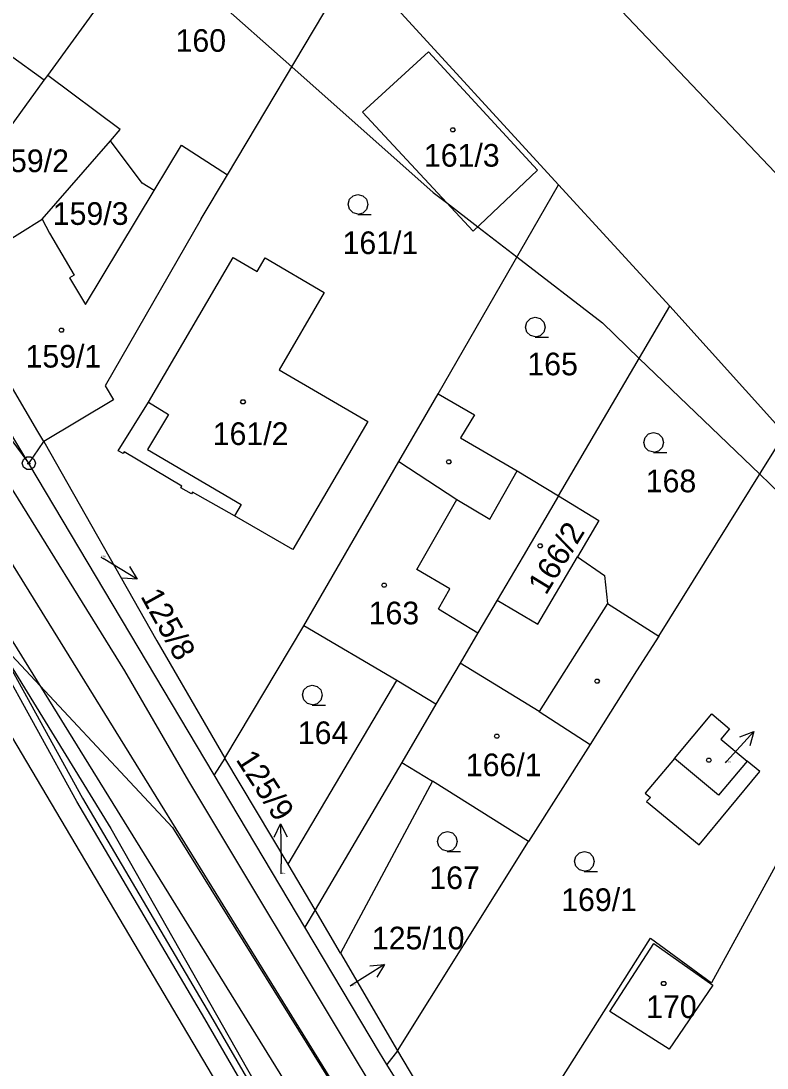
# Model space of a CAD drawing. Extents: x -755359 to -754474, y -1162585 to -1161655.
# Drawn here: x -754813.8 to -754757.8, y -1161904.8 to -1161826.3 of the extents above; entities that cross this region are included whole.
import ezdxf

# ---------------------------------------------------------------- set-up
doc = ezdxf.new("R2010")
doc.units = 0
for name, color, linetype in [('Vrstva 1', 7, 'Continuous'), ('Vrstva 11', 7, 'Continuous'), ('Vrstva 12', 7, 'Continuous'), ('Vrstva 13', 7, 'Continuous'), ('Vrstva 2', 7, 'Continuous'), ('Vrstva 3', 7, 'Continuous'), ('Vrstva 4', 7, 'Continuous'), ('Vrstva 5', 7, 'Continuous'), ('Vrstva 7', 7, 'Continuous'), ('Vrstva 8', 7, 'Continuous')]:
    doc.layers.add(name, color=color, linetype=linetype)

msp = doc.modelspace()

# ---------------------------------------------------------------- linework, layer by layer
at = {"layer": 'Vrstva 1'}
for p, q in [((-754811.79, -1161830.35), (-754798.38, -1161811.92)), ((-754776.63, -1161817.12), (-754756.21, -1161838.63)), ((-754798.29, -1161837.8), (-754788.76, -1161821.82)), ((-754773.44, -1161838.56), (-754788.76, -1161821.82)), ((-754812.05, -1161830.7), (-754814.68, -1161828.79)), ((-754788.15, -1161833.11), (-754783.2, -1161828.58)), ((-754783.2, -1161828.58), (-754775, -1161837.46)), ((-754812.05, -1161830.7), (-754811.79, -1161830.35)), ((-754806.35, -1161834.41), (-754811.79, -1161830.35)), ((-754817.18, -1161837.76), (-754812.05, -1161830.7)), ((-754779.84, -1161842.04), (-754788.15, -1161833.11)), ((-754807.07, -1161835.24), (-754806.35, -1161834.41)), ((-754812.21, -1161841.14), (-754807.07, -1161835.24)), ((-754804.69, -1161838.44), (-754807.07, -1161835.24)), ((-754803.79, -1161838.98), (-754801.73, -1161835.57)), ((-754801.73, -1161835.57), (-754798.29, -1161837.8)), ((-754775, -1161837.46), (-754779.84, -1161842.04)), ((-754803.79, -1161838.98), (-754804.69, -1161838.44)), ((-754800.26, -1161841.1), (-754798.29, -1161837.8)), ((-754808.94, -1161847.54), (-754803.79, -1161838.98)), ((-754782.47, -1161854.25), (-754773.44, -1161838.56)), ((-754765.06, -1161847.67), (-754773.44, -1161838.56)), ((-754819.29, -1161845.52), (-754812.21, -1161841.14)), ((-754812.21, -1161841.14), (-754811.66, -1161842.17)), ((-754800.26, -1161841.1), (-754807.47, -1161853.63)), ((-754811.66, -1161842.17), (-754809.8, -1161845.34)), ((-754813.2, -1161859.46), (-754822.56, -1161844)), ((-754804.23, -1161854.87), (-754797.87, -1161844.01)), ((-754797.87, -1161844.01), (-754796.07, -1161845.06)), ((-754796.07, -1161845.06), (-754795.46, -1161844.03)), ((-754795.46, -1161844.03), (-754791.02, -1161846.63)), ((-754823.68, -1161845.48), (-754813.2, -1161859.46)), ((-754809.8, -1161845.34), (-754810.15, -1161845.54)), ((-754810.15, -1161845.54), (-754808.94, -1161847.54)), ((-754812.54, -1161857.08), (-754818.72, -1161846.5)), ((-754791.02, -1161846.63), (-754794.41, -1161852.43)), ((-754773.43, -1161861.9), (-754765.06, -1161847.67)), ((-754756.43, -1161857.25), (-754765.06, -1161847.67)), ((-754794.41, -1161852.43), (-754787.75, -1161856.33)), ((-754807.47, -1161853.63), (-754806.84, -1161854.7)), ((-754806.84, -1161854.7), (-754812.09, -1161857.83)), ((-754806.49, -1161858.53), (-754804.23, -1161854.87)), ((-754783.47, -1161855.97), (-754782.47, -1161854.25)), ((-754782.47, -1161854.25), (-754779.75, -1161855.81)), ((-754779.75, -1161855.81), (-754780.79, -1161857.54)), ((-754787.75, -1161856.33), (-754793.37, -1161865.92)), ((-754785.42, -1161859.33), (-754783.47, -1161855.97)), ((-754812.09, -1161857.83), (-754812.54, -1161857.08)), ((-754765.9, -1161872.42), (-754756.43, -1161857.25)), ((-754813.2, -1161859.46), (-754812.09, -1161857.83)), ((-754812.09, -1161857.83), (-754803.59, -1161872.79)), ((-754780.79, -1161857.54), (-754776.54, -1161860.02)), ((-754806.12, -1161858.72), (-754806.49, -1161858.53)), ((-754806.04, -1161858.59), (-754806.12, -1161858.72)), ((-754801.71, -1161861.16), (-754806.04, -1161858.59)), ((-754799.29, -1161882.83), (-754813.2, -1161859.46)), ((-754792.56, -1161871.65), (-754785.42, -1161859.33)), ((-754776.54, -1161860.02), (-754773.43, -1161861.9)), ((-754801.78, -1161861.29), (-754801.71, -1161861.16)), ((-754800.98, -1161861.74), (-754801.78, -1161861.29)), ((-754800.91, -1161861.61), (-754800.98, -1161861.74)), ((-754797.77, -1161863.4), (-754800.91, -1161861.61)), ((-754773.43, -1161861.9), (-754776.09, -1161866.43)), ((-754773.43, -1161861.9), (-754770.39, -1161863.74)), ((-754793.37, -1161865.92), (-754797.77, -1161863.4)), ((-754770.39, -1161863.74), (-754772.01, -1161866.48)), ((-754823.33, -1161865.1), (-754790.69, -1161920.17)), ((-754776.09, -1161866.43), (-754778.04, -1161869.74)), ((-754774.99, -1161871.53), (-754772.01, -1161866.48)), ((-754772.01, -1161866.48), (-754769.98, -1161867.88)), ((-754769.98, -1161867.88), (-754769.74, -1161869.98)), ((-754745.52, -1161868.38), (-754761.94, -1161898.46)), ((-754778.04, -1161869.74), (-754779.48, -1161872.18)), ((-754778.04, -1161869.74), (-754774.99, -1161871.53)), ((-754769.74, -1161869.98), (-754765.9, -1161872.42)), ((-754798.49, -1161881.58), (-754792.56, -1161871.65)), ((-754785.56, -1161875.75), (-754792.56, -1161871.65)), ((-754779.48, -1161872.18), (-754780.81, -1161874.45)), ((-754803.59, -1161872.79), (-754798.49, -1161881.58)), ((-754765.9, -1161872.42), (-754767.56, -1161875.03)), ((-754780.81, -1161874.45), (-754782.63, -1161877.54)), ((-754767.56, -1161875.03), (-754771.06, -1161880.55)), ((-754793.74, -1161889.55), (-754785.56, -1161875.75)), ((-754782.63, -1161877.54), (-754785.2, -1161881.91)), ((-754764.73, -1161881.6), (-754761.92, -1161878.26)), ((-754761.92, -1161878.26), (-754760.59, -1161879.39)), ((-754760.59, -1161879.39), (-754761.24, -1161880.16)), ((-754761.24, -1161880.16), (-754759.27, -1161881.81)), ((-754771.06, -1161880.55), (-754775.69, -1161887.84)), ((-754798.49, -1161881.58), (-754799.29, -1161882.83)), ((-754793.74, -1161889.55), (-754798.49, -1161881.58)), ((-754761.41, -1161884.36), (-754764.73, -1161881.6)), ((-754785.2, -1161881.91), (-754791.71, -1161892.97)), ((-754759.27, -1161881.81), (-754761.41, -1161884.36)), ((-754792.47, -1161894.28), (-754799.29, -1161882.83)), ((-754782.9, -1161883.31), (-754789.8, -1161896.23)), ((-754775.69, -1161887.84), (-754782.9, -1161883.31)), ((-754785.52, -1161903.56), (-754775.69, -1161887.84)), ((-754791.71, -1161892.97), (-754793.74, -1161889.55)), ((-754791.71, -1161892.97), (-754792.47, -1161894.28)), ((-754789.8, -1161896.23), (-754791.71, -1161892.97)), ((-754786.88, -1161903.67), (-754792.47, -1161894.28)), ((-754778.9, -1161914.6), (-754766.52, -1161895.09)), ((-754766.52, -1161895.09), (-754761.94, -1161898.46)), ((-754769.57, -1161900.59), (-754766.26, -1161895.5)), ((-754766.26, -1161895.5), (-754761.83, -1161898.63)), ((-754789.8, -1161896.23), (-754785.52, -1161903.56)), ((-754761.83, -1161898.63), (-754765.12, -1161903.44)), ((-754765.12, -1161903.44), (-754769.57, -1161900.59)), ((-754786.32, -1161904.57), (-754786.88, -1161903.67)), ((-754785.52, -1161903.56), (-754786.32, -1161904.57)), ((-754785.52, -1161903.56), (-754778.9, -1161914.6)), ((-754779.53, -1161915.51), (-754786.32, -1161904.57))]:
    msp.add_line(p, q, dxfattribs=at)
at = {"layer": 'Vrstva 11'}
for p, q in [((-754800.99, -1161823.01), (-754793.46, -1161829.69)), ((-754793.46, -1161829.69), (-754782.83, -1161839.12)), ((-754782.83, -1161839.12), (-754781.84, -1161839.89)), ((-754781.84, -1161839.89), (-754779.48, -1161841.7)), ((-754779.48, -1161841.7), (-754776.55, -1161843.96)), ((-754776.55, -1161843.96), (-754770.13, -1161848.91)), ((-754770.13, -1161848.91), (-754767.36, -1161851.58)), ((-754767.36, -1161851.58), (-754758.32, -1161860.28)), ((-754758.32, -1161860.28), (-754747.03, -1161871.15)), ((-754825.44, -1161862.19), (-754802.43, -1161886.78)), ((-754802.43, -1161886.78), (-754764.12, -1161948.35))]:
    msp.add_line(p, q, dxfattribs=at)
at = {"layer": 'Vrstva 12'}
for p, q in [((-754788.15, -1161833.11), (-754783.2, -1161828.58)), ((-754783.2, -1161828.58), (-754775, -1161837.46)), ((-754779.84, -1161842.04), (-754788.15, -1161833.11)), ((-754803.79, -1161838.98), (-754801.73, -1161835.57)), ((-754801.73, -1161835.57), (-754798.29, -1161837.8)), ((-754775, -1161837.46), (-754779.84, -1161842.04)), ((-754800.26, -1161841.1), (-754798.29, -1161837.8)), ((-754808.94, -1161847.54), (-754803.79, -1161838.98)), ((-754819.29, -1161845.52), (-754812.21, -1161841.14)), ((-754812.21, -1161841.14), (-754811.66, -1161842.17)), ((-754800.26, -1161841.1), (-754807.47, -1161853.63)), ((-754811.66, -1161842.17), (-754809.8, -1161845.34)), ((-754804.23, -1161854.87), (-754797.87, -1161844.01)), ((-754797.87, -1161844.01), (-754796.07, -1161845.06)), ((-754796.07, -1161845.06), (-754795.46, -1161844.03)), ((-754795.46, -1161844.03), (-754791.02, -1161846.63)), ((-754809.8, -1161845.34), (-754810.15, -1161845.54)), ((-754810.15, -1161845.54), (-754808.94, -1161847.54)), ((-754812.54, -1161857.08), (-754818.72, -1161846.5)), ((-754791.02, -1161846.63), (-754794.41, -1161852.43)), ((-754794.41, -1161852.43), (-754787.75, -1161856.33)), ((-754807.47, -1161853.63), (-754806.84, -1161854.7)), ((-754806.84, -1161854.7), (-754812.09, -1161857.83)), ((-754804.23, -1161854.87), (-754802.72, -1161855.78)), ((-754802.72, -1161855.78), (-754804.3, -1161858.42)), ((-754787.75, -1161856.33), (-754793.37, -1161865.92)), ((-754812.09, -1161857.83), (-754812.54, -1161857.08)), ((-754804.3, -1161858.42), (-754797.27, -1161862.54)), ((-754792.56, -1161871.65), (-754785.42, -1161859.33)), ((-754785.42, -1161859.33), (-754781.07, -1161862.16)), ((-754773.43, -1161861.9), (-754776.09, -1161866.43)), ((-754773.43, -1161861.9), (-754770.39, -1161863.74)), ((-754797.27, -1161862.54), (-754797.77, -1161863.4)), ((-754784.08, -1161867.42), (-754781.07, -1161862.16)), ((-754793.37, -1161865.92), (-754797.77, -1161863.4)), ((-754770.39, -1161863.74), (-754772.01, -1161866.48)), ((-754776.09, -1161866.43), (-754778.04, -1161869.74)), ((-754774.99, -1161871.53), (-754772.01, -1161866.48)), ((-754781.58, -1161868.87), (-754784.08, -1161867.42)), ((-754782.45, -1161870.38), (-754781.58, -1161868.87)), ((-754778.04, -1161869.74), (-754774.99, -1161871.53)), ((-754782.45, -1161870.38), (-754779.48, -1161872.18)), ((-754785.56, -1161875.75), (-754792.56, -1161871.65)), ((-754779.48, -1161872.18), (-754780.81, -1161874.45)), ((-754780.81, -1161874.45), (-754782.63, -1161877.54)), ((-754780.81, -1161874.45), (-754782.63, -1161877.54)), ((-754774.88, -1161878.09), (-754780.81, -1161874.45)), ((-754782.63, -1161877.54), (-754785.56, -1161875.75)), ((-754782.63, -1161877.54), (-754785.2, -1161881.91)), ((-754774.88, -1161878.09), (-754771.06, -1161880.55)), ((-754764.73, -1161881.6), (-754761.92, -1161878.26)), ((-754761.92, -1161878.26), (-754760.59, -1161879.39)), ((-754760.59, -1161879.39), (-754761.24, -1161880.16)), ((-754761.24, -1161880.16), (-754759.27, -1161881.81)), ((-754771.06, -1161880.55), (-754775.69, -1161887.84)), ((-754761.41, -1161884.36), (-754764.73, -1161881.6)), ((-754785.2, -1161881.91), (-754782.9, -1161883.31)), ((-754759.27, -1161881.81), (-754761.41, -1161884.36)), ((-754775.69, -1161887.84), (-754782.9, -1161883.31)), ((-754769.57, -1161900.59), (-754766.26, -1161895.5)), ((-754766.26, -1161895.5), (-754761.83, -1161898.63)), ((-754761.83, -1161898.63), (-754765.12, -1161903.44)), ((-754765.12, -1161903.44), (-754769.57, -1161900.59))]:
    msp.add_line(p, q, dxfattribs=at)
at = {"layer": 'Vrstva 13'}
for p, q in [((-754832.48, -1161837.94), (-754785.36, -1161914.05)), ((-754788.28, -1161915.03), (-754834.82, -1161839.85)), ((-754809.61, -1161884.83), (-754816.58, -1161872.22)), ((-754816.08, -1161872.1), (-754809.17, -1161884.59)), ((-754799.99, -1161901.15), (-754809.61, -1161884.83)), ((-754809.17, -1161884.59), (-754799.57, -1161900.89)), ((-754789.54, -1161919.07), (-754799.99, -1161901.15)), ((-754799.57, -1161900.89), (-754788.96, -1161919.06))]:
    msp.add_line(p, q, dxfattribs=at)
at = {"layer": 'Vrstva 3'}
for points in [[(-754788.48, -1161840.75), (-754788.86, -1161840.65), (-754789.13, -1161840.38), (-754789.23, -1161840.01), (-754789.13, -1161839.64), (-754788.86, -1161839.37), (-754788.49, -1161839.27), (-754788.12, -1161839.37), (-754787.85, -1161839.64), (-754787.75, -1161840.02), (-754787.85, -1161840.4), (-754788.12, -1161840.67), (-754788.5, -1161840.77), (-754787.5, -1161840.77)], [(-754775.16, -1161849.97), (-754775.54, -1161849.87), (-754775.81, -1161849.6), (-754775.91, -1161849.23), (-754775.81, -1161848.86), (-754775.54, -1161848.59), (-754775.17, -1161848.49), (-754774.8, -1161848.59), (-754774.53, -1161848.86), (-754774.43, -1161849.24), (-754774.53, -1161849.62), (-754774.8, -1161849.89), (-754775.18, -1161849.99), (-754774.18, -1161849.99)], [(-754766.28, -1161858.63), (-754766.66, -1161858.53), (-754766.93, -1161858.26), (-754767.03, -1161857.89), (-754766.93, -1161857.52), (-754766.66, -1161857.25), (-754766.29, -1161857.15), (-754765.92, -1161857.25), (-754765.65, -1161857.52), (-754765.55, -1161857.9), (-754765.65, -1161858.28), (-754765.92, -1161858.55), (-754766.3, -1161858.65), (-754765.3, -1161858.65)], [(-754791.91, -1161877.58), (-754792.29, -1161877.48), (-754792.56, -1161877.21), (-754792.66, -1161876.84), (-754792.56, -1161876.47), (-754792.29, -1161876.2), (-754791.92, -1161876.1), (-754791.55, -1161876.2), (-754791.28, -1161876.47), (-754791.18, -1161876.85), (-754791.28, -1161877.23), (-754791.55, -1161877.5), (-754791.93, -1161877.6), (-754790.93, -1161877.6)], [(-754781.76, -1161888.57), (-754782.14, -1161888.47), (-754782.41, -1161888.2), (-754782.51, -1161887.83), (-754782.41, -1161887.46), (-754782.14, -1161887.19), (-754781.77, -1161887.09), (-754781.4, -1161887.19), (-754781.13, -1161887.46), (-754781.03, -1161887.84), (-754781.13, -1161888.22), (-754781.4, -1161888.49), (-754781.78, -1161888.59), (-754780.78, -1161888.59)], [(-754771.47, -1161890.07), (-754771.85, -1161889.97), (-754772.12, -1161889.7), (-754772.22, -1161889.33), (-754772.12, -1161888.96), (-754771.85, -1161888.69), (-754771.48, -1161888.59), (-754771.11, -1161888.69), (-754770.84, -1161888.96), (-754770.74, -1161889.34), (-754770.84, -1161889.72), (-754771.11, -1161889.99), (-754771.49, -1161890.09), (-754770.49, -1161890.09)]]:
    msp.add_lwpolyline(points, dxfattribs=at)
at = {"layer": 'Vrstva 4'}
for p, q in [((-754804.23, -1161854.87), (-754802.72, -1161855.78)), ((-754802.72, -1161855.78), (-754804.3, -1161858.42)), ((-754804.3, -1161858.42), (-754797.27, -1161862.54)), ((-754785.42, -1161859.33), (-754781.07, -1161862.16)), ((-754806, -1161875.03), (-754815.09, -1161860.38)), ((-754778.59, -1161863.64), (-754776.54, -1161860.02)), ((-754797.27, -1161862.54), (-754797.77, -1161863.4)), ((-754784.08, -1161867.42), (-754781.07, -1161862.16)), ((-754781.07, -1161862.16), (-754778.59, -1161863.64)), ((-754821.11, -1161863.98), (-754807.06, -1161886.86)), ((-754781.58, -1161868.87), (-754784.08, -1161867.42)), ((-754782.45, -1161870.38), (-754781.58, -1161868.87)), ((-754782.45, -1161870.38), (-754779.48, -1161872.18)), ((-754769.74, -1161869.98), (-754774.88, -1161878.09)), ((-754774.88, -1161878.09), (-754780.81, -1161874.45)), ((-754801.2, -1161883.32), (-754806, -1161875.03)), ((-754782.63, -1161877.54), (-754785.56, -1161875.75)), ((-754774.88, -1161878.09), (-754771.06, -1161880.55)), ((-754764.73, -1161881.6), (-754766.92, -1161884.22)), ((-754785.2, -1161881.91), (-754782.9, -1161883.31)), ((-754758.32, -1161882.6), (-754759.27, -1161881.81)), ((-754788.45, -1161904.52), (-754801.2, -1161883.32)), ((-754762.86, -1161888.1), (-754758.32, -1161882.6)), ((-754766.92, -1161884.22), (-754766.53, -1161884.54)), ((-754766.53, -1161884.54), (-754766.81, -1161884.84)), ((-754766.81, -1161884.84), (-754762.86, -1161888.1)), ((-754807.06, -1161886.86), (-754795.46, -1161907.28)), ((-754777, -1161923.33), (-754788.45, -1161904.52))]:
    msp.add_line(p, q, dxfattribs=at)
at = {"layer": 'Vrstva 5'}
for points in [[(-754781.28, -1161834.27), (-754781.19, -1161834.42), (-754781.28, -1161834.57), (-754781.46, -1161834.57), (-754781.55, -1161834.42), (-754781.46, -1161834.27)], [(-754810.67, -1161849.32), (-754810.58, -1161849.47), (-754810.67, -1161849.62), (-754810.85, -1161849.62), (-754810.94, -1161849.47), (-754810.85, -1161849.32)], [(-754797.03, -1161854.68), (-754796.94, -1161854.83), (-754797.03, -1161854.98), (-754797.21, -1161854.98), (-754797.3, -1161854.83), (-754797.21, -1161854.68)], [(-754781.58, -1161859.19), (-754781.49, -1161859.34), (-754781.58, -1161859.49), (-754781.76, -1161859.49), (-754781.85, -1161859.34), (-754781.76, -1161859.19)], [(-754774.72, -1161865.5), (-754774.63, -1161865.65), (-754774.72, -1161865.8), (-754774.9, -1161865.8), (-754774.99, -1161865.65), (-754774.9, -1161865.5)], [(-754786.43, -1161868.45), (-754786.34, -1161868.6), (-754786.43, -1161868.75), (-754786.61, -1161868.75), (-754786.7, -1161868.6), (-754786.61, -1161868.45)], [(-754770.44, -1161875.67), (-754770.35, -1161875.82), (-754770.44, -1161875.97), (-754770.62, -1161875.97), (-754770.71, -1161875.82), (-754770.62, -1161875.67)], [(-754777.97, -1161879.78), (-754777.88, -1161879.93), (-754777.97, -1161880.08), (-754778.15, -1161880.08), (-754778.24, -1161879.93), (-754778.15, -1161879.78)], [(-754762.05, -1161881.59), (-754761.96, -1161881.74), (-754762.05, -1161881.89), (-754762.23, -1161881.89), (-754762.32, -1161881.74), (-754762.23, -1161881.59)], [(-754765.44, -1161898.35), (-754765.35, -1161898.5), (-754765.44, -1161898.65), (-754765.62, -1161898.65), (-754765.71, -1161898.5), (-754765.62, -1161898.35)]]:
    msp.add_lwpolyline(points, close=True, dxfattribs=at)
at = {"layer": 'Vrstva 7'}
for p, q in [((-754807.81, -1161866.5), (-754807.63, -1161866.61)), ((-754805.059, -1161868.156), (-754807.63, -1161866.61)), ((-754758.772, -1161879.581), (-754760.78, -1161881.81)), ((-754760.89, -1161881.93), (-754760.78, -1161881.81)), ((-754794.311, -1161886.51), (-754794.26, -1161889.51)), ((-754794.25, -1161890.27), (-754794.26, -1161889.51)), ((-754786.496, -1161897.08), (-754789.04, -1161898.67)), ((-754789.07, -1161898.69), (-754789.04, -1161898.67))]:
    msp.add_line(p, q, dxfattribs=at)
for points in [[(-754805.658, -1161867.212), (-754805.059, -1161868.156), (-754806.174, -1161868.069)], [(-754759.813, -1161879.989), (-754758.772, -1161879.581), (-754759.07, -1161880.659)], [(-754794.794, -1161887.519), (-754794.311, -1161886.51), (-754793.794, -1161887.502)], [(-754787.609, -1161897.186), (-754786.496, -1161897.08), (-754787.079, -1161898.034)]]:
    msp.add_lwpolyline(points, dxfattribs=at)
at = {"layer": 'Vrstva 8'}
msp.add_line((-754813.32, -1161859.46), (-754813.08, -1161859.46), dxfattribs=at)
msp.add_lwpolyline([(-754813.05, -1161858.98), (-754812.8, -1161859.16), (-754812.7, -1161859.45), (-754812.8, -1161859.74), (-754813.05, -1161859.92), (-754813.36, -1161859.92), (-754813.61, -1161859.74), (-754813.71, -1161859.45), (-754813.61, -1161859.16), (-754813.36, -1161858.98)], close=True, dxfattribs=at)

# ---------------------------------------------------------------- texts
at = {"layer": 'Vrstva 2'}
for s, height, p in [('160', 1.7, (-754802.187, -1161828.57)), ('159/2', 1.7, (-754815.886, -1161837.6)), ('161/3', 1.7, (-754783.537, -1161837.19)), ('159/3', 1.7, (-754811.409, -1161841.56)), ('161/1', 1.7, (-754789.647, -1161843.75)), ('159/1', 1.7, (-754813.454, -1161852.27)), ('165', 1.7, (-754775.767, -1161852.85)), ('161/2', 1.7, (-754799.397, -1161858.08)), ('168', 1.7, (-754766.877, -1161861.63)), ('125/8', 0.1, (-754807.787, -1161866.5)), ('163', 1.7, (-754787.687, -1161871.54)), ('164', 1.7, (-754793.007, -1161880.53)), ('166/1', 1.7, (-754780.387, -1161882.94)), ('169/3', 0.1, (-754760.867, -1161881.93)), ('125/9', 0.1, (-754794.227, -1161890.27)), ('167', 1.7, (-754783.127, -1161891.41)), ('169/1', 1.7, (-754773.227, -1161893.06)), ('125/10', 0.1, (-754789.047, -1161898.69)), ('170', 1.7, (-754766.847, -1161901.09))]:
    msp.add_text(s, height=height, dxfattribs=at).set_placement(p)
msp.add_text('166/2', height=1.7, rotation=58.49899, dxfattribs=at).set_placement((-754774.375, -1161869.415))
at = {"layer": 'Vrstva 7'}
for s, rotation, p in [('125/8', 299.02667, (-754804.856, -1161869.428)), ('125/9', 302.98008, (-754797.706, -1161881.689))]:
    msp.add_text(s, height=1.7, rotation=rotation, dxfattribs=at).set_placement(p)
msp.add_text('125/10', height=1.7, dxfattribs=at).set_placement((-754787.447, -1161895.94))

doc.saveas('drawing.dxf')
